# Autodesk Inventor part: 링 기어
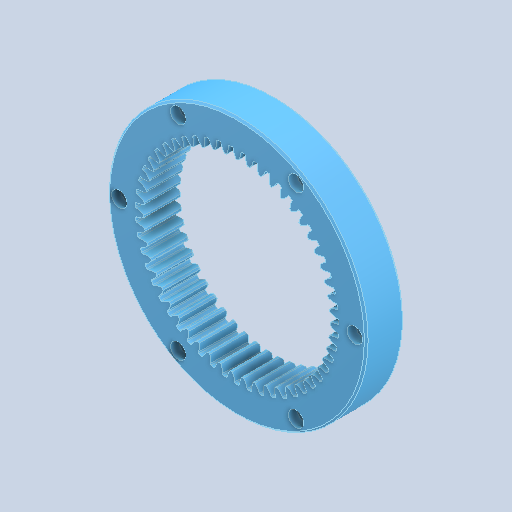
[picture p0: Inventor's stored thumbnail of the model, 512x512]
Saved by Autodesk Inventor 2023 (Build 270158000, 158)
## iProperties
Created: 2026-04
Part Number: 링 기어
Material: 강철, 합금
Document SubType Name: Modeling
Designer: home
Density: 7.73 g/cm^3
Appearance: 기본값
Author: jhkim
Sending System: Autodesk Inventor 2027
Preprocessor: ST-DEVELOPER v20.1
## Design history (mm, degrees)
feature "솔리드1"
node "솔리드2"
